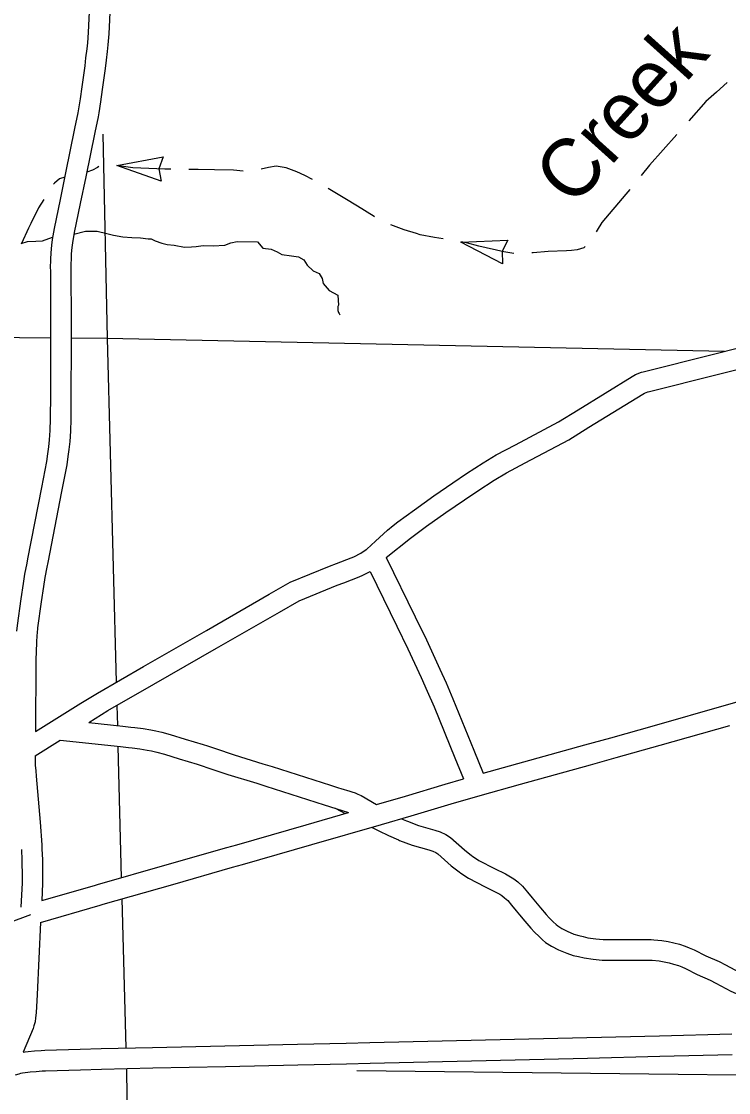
# Model space of a CAD drawing. Extents: x 1373094 to 1376427, y 1168361 to 1170494.
# Drawn here: x 1373845.2 to 1373931.1, y 1170254.2 to 1170384.4 of the extents above; entities that cross this region are included whole.
import ezdxf

# ---------------------------------------------------------------- set-up
doc = ezdxf.new("R2010")
doc.units = 0
doc.layers.add('R_Axis', color=7, linetype='Continuous')

msp = doc.modelspace()

# ---------------------------------------------------------------- linework, layer by layer
at = {"layer": 'R_Axis'}
for p, q in [((1373856.79, 1170366.88), (1373862.41, 1170367.94)), ((1373862.41, 1170367.94), (1373861.9, 1170366.49)), ((1373862.19, 1170364.98), (1373856.79, 1170366.88)), ((1373861.9, 1170366.49), (1373862.19, 1170364.98)), ((1373898.6, 1170357.56), (1373904.31, 1170357.82)), ((1373903.67, 1170354.93), (1373898.6, 1170357.56)), ((1373904.31, 1170357.82), (1373903.61, 1170356.46)), ((1373903.61, 1170356.46), (1373903.67, 1170354.93))]:
    msp.add_line(p, q, dxfattribs=at)
for points in [[(1373853.51, 1170388.63), (1373853.47, 1170386.42), (1373853.32, 1170383.04), (1373853.23, 1170381.78), (1373853.14, 1170381.05), (1373853.01, 1170379.98)], [(1373856.01, 1170388.58), (1373855.97, 1170386.34), (1373855.81, 1170382.9), (1373855.72, 1170381.54), (1373855.62, 1170380.75), (1373855.49, 1170379.68)], [(1373853.01, 1170379.98), (1373852.89, 1170378.98), (1373852.55, 1170376.46), (1373852.35, 1170374.97), (1373852.16, 1170373.75), (1373852.06, 1170373.29), (1373851.67, 1170371.39)], [(1373855.49, 1170379.68), (1373855.37, 1170378.66), (1373855.02, 1170376.12), (1373854.82, 1170374.62), (1373854.62, 1170373.3), (1373854.51, 1170372.78), (1373854.12, 1170370.88)], [(1373930.96, 1170376.96), (1373929.67, 1170375.81), (1373928.38, 1170374.64), (1373926.3, 1170372.31)], [(1373851.67, 1170371.39), (1373850.57, 1170365.99), (1373849.91, 1170362.77)], [(1373854.12, 1170370.88), (1373853.02, 1170365.49), (1373852.36, 1170362.26)], [(1373855.08, 1170370.69), (1373855.61, 1170345.9), (1373856.72, 1170304.09)], [(1373924.84, 1170370.66), (1373921.5, 1170366.92), (1373920.5, 1170365.68)], [(1373854.62, 1170366.77), (1373854.45, 1170366.63), (1373853.85, 1170366.31), (1373853.14, 1170366.08)], [(1373863.36, 1170366.43), (1373862.63, 1170366.45), (1373858.75, 1170366.58), (1373857.61, 1170366.78), (1373856.79, 1170366.88)], [(1373872.16, 1170366.21), (1373870.99, 1170366.3), (1373868.66, 1170366.37), (1373866.66, 1170366.41), (1373865.56, 1170366.41)], [(1373880.57, 1170365.17), (1373879.64, 1170365.65), (1373878.68, 1170366.11), (1373877.37, 1170366.6), (1373876.14, 1170366.81), (1373875.24, 1170366.64), (1373874.33, 1170366.44)], [(1373850.46, 1170365.45), (1373849.83, 1170365.27), (1373849.22, 1170364.75), (1373849.1, 1170364.6)], [(1373888.12, 1170360.66), (1373888.07, 1170360.69), (1373886.03, 1170361.94), (1373884.52, 1170362.87), (1373882.49, 1170364.1)], [(1373919.12, 1170363.97), (1373918.66, 1170363.41), (1373915.73, 1170359.96), (1373915.15, 1170359.01), (1373915.02, 1170358.82)], [(1373847.91, 1170362.75), (1373847.3, 1170361.73), (1373846.35, 1170359.85)], [(1373849.91, 1170362.77), (1373849.18, 1170359.22), (1373848.94, 1170357.89), (1373848.84, 1170357.19), (1373848.77, 1170356.29), (1373848.73, 1170355.51), (1373848.72, 1170355.08), (1373848.71, 1170354.79), (1373848.72, 1170353.81)], [(1373852.36, 1170362.26), (1373851.63, 1170358.75), (1373851.41, 1170357.5), (1373851.33, 1170356.91), (1373851.26, 1170356.13), (1373851.23, 1170355.43), (1373851.22, 1170355), (1373851.21, 1170354.75), (1373851.22, 1170353.83)], [(1373846.35, 1170359.85), (1373846.06, 1170359.27), (1373845.21, 1170357.41)], [(1373893.2, 1170358.6), (1373891.7, 1170359.05), (1373890.08, 1170359.67)], [(1373845.19, 1170357.41), (1373845.96, 1170357.65), (1373846.96, 1170357.7), (1373847.75, 1170357.73), (1373848.99, 1170358.19)], [(1373851.59, 1170358.55), (1373852.99, 1170358.89), (1373854.4, 1170358.91), (1373855.57, 1170358.63), (1373856.39, 1170358.41), (1373857.53, 1170358.2), (1373858.63, 1170358.13), (1373859.66, 1170358.1), (1373860.61, 1170357.98), (1373860.98, 1170357.97), (1373861.47, 1170357.73), (1373862.27, 1170357.45), (1373862.91, 1170357.3), (1373863.76, 1170357.2), (1373865, 1170356.95), (1373865.86, 1170357.01), (1373866.42, 1170357.05), (1373867.29, 1170357.17), (1373868.5, 1170357.13), (1373869.93, 1170357.22), (1373870.63, 1170357.47), (1373871.42, 1170357.66), (1373873.87, 1170357.59), (1373874.55, 1170356.82), (1373875.55, 1170356.71), (1373876.27, 1170356.4), (1373876.83, 1170356.05), (1373878.02, 1170355.92), (1373878.88, 1170355.77), (1373879.51, 1170355.43), (1373879.92, 1170354.76), (1373880.67, 1170354.07), (1373881.37, 1170353.75), (1373881.74, 1170353.14), (1373881.85, 1170352.54), (1373882.61, 1170351.71), (1373883.66, 1170351.14), (1373883.75, 1170349.93), (1373883.64, 1170349.74), (1373883.65, 1170349.27), (1373883.75, 1170349.04), (1373883.81, 1170348.89), (1373883.89, 1170348.74)], [(1373896.44, 1170357.98), (1373895.39, 1170358.14), (1373893.64, 1170358.47), (1373893.2, 1170358.6)], [(1373905.05, 1170356.18), (1373903.83, 1170356.41), (1373900.79, 1170357.08), (1373899.27, 1170357.47), (1373898.61, 1170357.6)], [(1373913.72, 1170357.06), (1373913.54, 1170356.89), (1373912.73, 1170356.63), (1373912.05, 1170356.54), (1373911.42, 1170356.51), (1373909.21, 1170356.42), (1373907.4, 1170356.28), (1373907.24, 1170356.26)], [(1373848.72, 1170353.81), (1373848.75, 1170348.15), (1373848.74, 1170345.02)], [(1373851.22, 1170353.83), (1373851.25, 1170348.16), (1373851.24, 1170345.01)], [(1373929.29, 1170343.97), (1373935.37, 1170345.49), (1373937.78, 1170346.17)], [(1373841.16, 1170346.01), (1373848.74, 1170345.95)], [(1373848.74, 1170345.02), (1373848.72, 1170338.94), (1373848.69, 1170336.23)], [(1373851.24, 1170345.01), (1373851.22, 1170338.92), (1373851.19, 1170336.21)], [(1373851.24, 1170345.93), (1373855.61, 1170345.9), (1373930.65, 1170344.31)], [(1373920.76, 1170341.83), (1373929.29, 1170343.97)], [(1373929.9, 1170341.54), (1373936.02, 1170343.08), (1373938.45, 1170343.76)], [(1373912.85, 1170337.19), (1373919.43, 1170341.26), (1373919.82, 1170341.49), (1373920.56, 1170341.78), (1373920.76, 1170341.83)], [(1373921.36, 1170339.4), (1373929.9, 1170341.54)], [(1373914.16, 1170335.07), (1373920.72, 1170339.11), (1373920.92, 1170339.23), (1373921.33, 1170339.4), (1373921.36, 1170339.4)], [(1373905.24, 1170332.95), (1373910.46, 1170335.72), (1373912.85, 1170337.19)], [(1373848.69, 1170336.23), (1373848.69, 1170336.1), (1373848.65, 1170334.7), (1373848.58, 1170333.55), (1373848.5, 1170332.68), (1373848.39, 1170331.86), (1373848.24, 1170330.93), (1373847.63, 1170327.74)], [(1373851.19, 1170336.21), (1373851.19, 1170336.05), (1373851.15, 1170334.59), (1373851.08, 1170333.36), (1373850.98, 1170332.39), (1373850.86, 1170331.51), (1373850.71, 1170330.5), (1373850.08, 1170327.27)], [(1373906.41, 1170330.74), (1373911.71, 1170333.55), (1373914.16, 1170335.07)], [(1373897.61, 1170328.31), (1373899.29, 1170329.46), (1373901.32, 1170330.76), (1373902.9, 1170331.71), (1373905.24, 1170332.95)], [(1373899.02, 1170326.24), (1373900.67, 1170327.37), (1373902.64, 1170328.63), (1373904.13, 1170329.53), (1373906.41, 1170330.74)], [(1373890.38, 1170323.14), (1373890.95, 1170323.6), (1373892.95, 1170325.06), (1373895.33, 1170326.76), (1373897.61, 1170328.31)], [(1373847.63, 1170327.74), (1373845.95, 1170319.1)], [(1373850.08, 1170327.27), (1373848.41, 1170318.63)], [(1373889.51, 1170319.25), (1373892.47, 1170321.61), (1373894.41, 1170323.04), (1373896.76, 1170324.71), (1373899.02, 1170326.24)], [(1373883.47, 1170318.51), (1373885.28, 1170319.21), (1373885.61, 1170319.35), (1373886.43, 1170319.79), (1373887.1, 1170320.21), (1373887.19, 1170320.28), (1373888.24, 1170321.23), (1373889.69, 1170322.59), (1373890.38, 1170323.14)], [(1373845.95, 1170319.1), (1373845.85, 1170318.56), (1373845.59, 1170317.21), (1373845.42, 1170316.08), (1373845.15, 1170314.24), (1373844.68, 1170311), (1373844.61, 1170310.29)], [(1373889.51, 1170319.25), (1373893.06, 1170312.03)], [(1373848.41, 1170318.63), (1373848.3, 1170318.08), (1373848.05, 1170316.8), (1373847.9, 1170315.72), (1373847.62, 1170313.88), (1373847.17, 1170310.7), (1373847.1, 1170310.05)], [(1373875.31, 1170314.78), (1373877.86, 1170316.25), (1373882.64, 1170318.19), (1373883.47, 1170318.51)], [(1373884.37, 1170316.18), (1373886.24, 1170316.9), (1373886.7, 1170317.1), (1373887.56, 1170317.55)], [(1373887.56, 1170317.55), (1373890.81, 1170310.92)], [(1373876.55, 1170312.61), (1373878.96, 1170314), (1373883.56, 1170315.87), (1373884.37, 1170316.18)], [(1373867.68, 1170310.39), (1373875.31, 1170314.78)], [(1373868.92, 1170308.23), (1373876.55, 1170312.61)], [(1373893.06, 1170312.03), (1373894.42, 1170309.24), (1373896.06, 1170305.69), (1373896.8, 1170304)], [(1373847.1, 1170310.05), (1373847.08, 1170309.8), (1373847.02, 1170308.93), (1373846.95, 1170306.76), (1373846.94, 1170303.35), (1373846.93, 1170301.37)], [(1373860.05, 1170306.01), (1373867.68, 1170310.39)], [(1373890.81, 1170310.92), (1373892.17, 1170308.17), (1373893.78, 1170304.66), (1373894.51, 1170303)], [(1373861.29, 1170303.84), (1373868.92, 1170308.23)], [(1373852.42, 1170301.53), (1373854.44, 1170302.78), (1373860.05, 1170306.01)], [(1373853.39, 1170299.19), (1373855.72, 1170300.64), (1373861.29, 1170303.84)], [(1373896.8, 1170304), (1373897.64, 1170302.07), (1373900.18, 1170295.84)], [(1373930.6, 1170301.25), (1373939.07, 1170303.66)], [(1373894.51, 1170303), (1373895.34, 1170301.1), (1373897.87, 1170294.9)], [(1373846.92, 1170298.12), (1373852.42, 1170301.53)], [(1373846.93, 1170301.37), (1373846.92, 1170298.12)], [(1373856.79, 1170301.25), (1373856.86, 1170298.83)], [(1373922.14, 1170298.85), (1373930.6, 1170301.25)], [(1373853.39, 1170299.19), (1373857.53, 1170298.76), (1373858.51, 1170298.64)], [(1373858.51, 1170298.64), (1373858.98, 1170298.59), (1373859.98, 1170298.45), (1373860.91, 1170298.3), (1373861.54, 1170298.18), (1373862.26, 1170298.01), (1373863.27, 1170297.74), (1373865.09, 1170297.19), (1373867.27, 1170296.52)], [(1373913.68, 1170296.47), (1373916.81, 1170297.33), (1373922.14, 1170298.85)], [(1373922.82, 1170296.44), (1373931.29, 1170298.85)], [(1373846.86, 1170295.14), (1373849.92, 1170297.04)], [(1373849.92, 1170297.04), (1373857.25, 1170296.27), (1373858.23, 1170296.16)], [(1373856.92, 1170296.3), (1373857.34, 1170280.34)], [(1373858.23, 1170296.16), (1373858.67, 1170296.11), (1373859.6, 1170295.98), (1373860.48, 1170295.83), (1373861.02, 1170295.74), (1373861.65, 1170295.59), (1373862.59, 1170295.34), (1373864.36, 1170294.8), (1373866.54, 1170294.13)], [(1373867.27, 1170296.52), (1373867.81, 1170296.36), (1373868.79, 1170296.02), (1373871.05, 1170295.27), (1373874.55, 1170294.19), (1373875.67, 1170293.84)], [(1373900.18, 1170295.84), (1373901.32, 1170293.04)], [(1373901.32, 1170293.04), (1373913.68, 1170296.47)], [(1373914.34, 1170294.06), (1373917.48, 1170294.93), (1373922.82, 1170296.44)], [(1373846.86, 1170295.14), (1373846.86, 1170294.74), (1373846.89, 1170294.02), (1373846.94, 1170293.33), (1373846.99, 1170292.68)], [(1373866.54, 1170294.13), (1373867.04, 1170293.98), (1373867.99, 1170293.65), (1373870.29, 1170292.89), (1373873.8, 1170291.81), (1373874.91, 1170291.45)], [(1373897.87, 1170294.9), (1373898.91, 1170292.35)], [(1373875.67, 1170293.84), (1373882.76, 1170291.57), (1373883.74, 1170291.26), (1373884.02, 1170291.18)], [(1373905.86, 1170291.71), (1373914.34, 1170294.06)], [(1373846.99, 1170292.68), (1373847.47, 1170287.07), (1373847.68, 1170284.34), (1373847.7, 1170283.86)], [(1373888.36, 1170289.24), (1373891.86, 1170290.25), (1373896.71, 1170291.69)], [(1373896.71, 1170291.69), (1373898.91, 1170292.35)], [(1373897.43, 1170289.3), (1373900.93, 1170290.34), (1373905.86, 1170291.71)], [(1373874.91, 1170291.45), (1373882, 1170289.19), (1373884.94, 1170288.26)], [(1373884.02, 1170291.18), (1373885.09, 1170290.87), (1373885.37, 1170290.78), (1373885.74, 1170290.65), (1373886.09, 1170290.51), (1373886.47, 1170290.32), (1373888.36, 1170289.24)], [(1373888.97, 1170286.81), (1373892.57, 1170287.85), (1373897.43, 1170289.3)], [(1373879.82, 1170286.78), (1373884.94, 1170288.26)], [(1373883.32, 1170288.78), (1373884.54, 1170288.14)], [(1373871.37, 1170284.35), (1373879.82, 1170286.78)], [(1373880.51, 1170284.38), (1373888.97, 1170286.81)], [(1373887.75, 1170286.46), (1373888.63, 1170286.03), (1373889.8, 1170285.46), (1373891.01, 1170284.94)], [(1373891.38, 1170287.5), (1373891.99, 1170287.24)], [(1373891.99, 1170287.24), (1373892.1, 1170287.2), (1373893.46, 1170286.67), (1373895.43, 1170286.11), (1373896.09, 1170285.9), (1373896.76, 1170285.6), (1373897.33, 1170285.22), (1373899.02, 1170283.72), (1373899.91, 1170283.04)], [(1373845.2, 1170283.76), (1373845.25, 1170282.45), (1373845.28, 1170280.41), (1373845.28, 1170279.71), (1373845.13, 1170276.74)], [(1373847.7, 1170283.86), (1373847.75, 1170282.52), (1373847.78, 1170280.42), (1373847.78, 1170279.65), (1373847.67, 1170277.55)], [(1373862.91, 1170281.93), (1373870.15, 1170284), (1373871.37, 1170284.35)], [(1373872.06, 1170281.95), (1373880.51, 1170284.38)], [(1373891.01, 1170284.94), (1373891.16, 1170284.88), (1373892.67, 1170284.3), (1373894.72, 1170283.72), (1373895.2, 1170283.56), (1373895.54, 1170283.41), (1373895.79, 1170283.24), (1373897.43, 1170281.79), (1373898.39, 1170281.06)], [(1373899.91, 1170283.04), (1373900.03, 1170282.94), (1373900.8, 1170282.44), (1373902.7, 1170281.46), (1373904.01, 1170280.8), (1373904.64, 1170280.46), (1373905.03, 1170280.19), (1373905.51, 1170279.83), (1373906.08, 1170279.32), (1373906.7, 1170278.59), (1373907.27, 1170277.88)], [(1373854.45, 1170279.51), (1373862.91, 1170281.93)], [(1373863.59, 1170279.53), (1373870.84, 1170281.6), (1373872.06, 1170281.95)], [(1373898.39, 1170281.06), (1373898.58, 1170280.91), (1373899.54, 1170280.28), (1373901.57, 1170279.23), (1373902.86, 1170278.58), (1373903.34, 1170278.32), (1373903.57, 1170278.17), (1373903.91, 1170277.91), (1373904.29, 1170277.57), (1373904.77, 1170277), (1373905.31, 1170276.32)], [(1373847.67, 1170277.55), (1373854.07, 1170279.41), (1373854.45, 1170279.51)], [(1373855.13, 1170277.11), (1373863.59, 1170279.53)], [(1373857.41, 1170277.76), (1373857.89, 1170259.65)], [(1373907.27, 1170277.88), (1373907.65, 1170277.39), (1373908.26, 1170276.68), (1373908.95, 1170275.87), (1373909.34, 1170275.47), (1373909.82, 1170274.99), (1373910.18, 1170274.67), (1373910.38, 1170274.49), (1373910.88, 1170274.17), (1373911.53, 1170273.83), (1373912.33, 1170273.49), (1373912.93, 1170273.3), (1373913.44, 1170273.18)], [(1373811.61, 1170265.69), (1373815.9, 1170266.81), (1373819.7, 1170267.91), (1373824.44, 1170269.4), (1373841.28, 1170274.05), (1373843.63, 1170274.85), (1373846.34, 1170275.86)], [(1373847.54, 1170274.91), (1373854.76, 1170277), (1373855.13, 1170277.11)], [(1373905.31, 1170276.32), (1373905.72, 1170275.81), (1373906.36, 1170275.05), (1373907.1, 1170274.19), (1373907.56, 1170273.71), (1373908.1, 1170273.18), (1373908.52, 1170272.79), (1373908.89, 1170272.48), (1373909.61, 1170272.01), (1373910.47, 1170271.56), (1373911.46, 1170271.15), (1373912.26, 1170270.89), (1373912.89, 1170270.75)], [(1373847.54, 1170274.91), (1373847.1, 1170266.16)], [(1373913.44, 1170273.18), (1373914.04, 1170273.05), (1373914.99, 1170272.91), (1373915.89, 1170272.82), (1373921.73, 1170272.82), (1373922.03, 1170272.8)], [(1373922.03, 1170272.8), (1373923.03, 1170272.71), (1373923.79, 1170272.58), (1373924.49, 1170272.43), (1373925.15, 1170272.25), (1373925.87, 1170272.01), (1373926.35, 1170271.82), (1373926.96, 1170271.58), (1373928.38, 1170270.83), (1373929.98, 1170270.14), (1373930.74, 1170269.74)], [(1373912.89, 1170270.75), (1373913.59, 1170270.59), (1373914.68, 1170270.43), (1373915.77, 1170270.32), (1373921.63, 1170270.32), (1373921.83, 1170270.3)], [(1373921.83, 1170270.3), (1373922.71, 1170270.23), (1373923.3, 1170270.12), (1373923.9, 1170270), (1373924.44, 1170269.85), (1373925.03, 1170269.66), (1373925.43, 1170269.5), (1373925.9, 1170269.31), (1373927.3, 1170268.57), (1373928.9, 1170267.89), (1373929.56, 1170267.53)], [(1373930.74, 1170269.74), (1373932.49, 1170268.81), (1373935.02, 1170267.7), (1373935.66, 1170267.34), (1373936.1, 1170267.04), (1373936.84, 1170266.4), (1373937.73, 1170265.55), (1373937.85, 1170265.47), (1373938.14, 1170265.34), (1373938.13, 1170265.34)], [(1373929.56, 1170267.53), (1373931.4, 1170266.56), (1373933.91, 1170265.45), (1373934.35, 1170265.21), (1373934.57, 1170265.06), (1373935.16, 1170264.55), (1373936.17, 1170263.58), (1373936.66, 1170263.27), (1373937.16, 1170263.04), (1373937.18, 1170263.03)], [(1373847.1, 1170266.16), (1373846.99, 1170263.93), (1373846.93, 1170263.32), (1373846.86, 1170262.83), (1373846.73, 1170262.34), (1373846.62, 1170262.02), (1373845.4, 1170259.15)], [(1373878.73, 1170260.1), (1373884.65, 1170260.23), (1373887.53, 1170260.3)], [(1373887.53, 1170260.3), (1373896.32, 1170260.51)], [(1373896.32, 1170260.51), (1373905.12, 1170260.72)], [(1373905.12, 1170260.72), (1373913.92, 1170260.93)], [(1373913.92, 1170260.93), (1373922.72, 1170261.14)], [(1373922.72, 1170261.14), (1373931.51, 1170261.35)], [(1373845.4, 1170259.15), (1373845.67, 1170259.18), (1373846.01, 1170259.22), (1373846.79, 1170259.3), (1373847.6, 1170259.35), (1373848.04, 1170259.37), (1373852.33, 1170259.5)], [(1373852.33, 1170259.5), (1373854.89, 1170259.58), (1373861.14, 1170259.72)], [(1373861.14, 1170259.72), (1373869.93, 1170259.91)], [(1373869.93, 1170259.91), (1373878.73, 1170260.1)], [(1373878.79, 1170257.6), (1373884.71, 1170257.73), (1373887.59, 1170257.8)], [(1373887.59, 1170257.8), (1373896.38, 1170258.01)], [(1373896.38, 1170258.01), (1373905.18, 1170258.22)], [(1373905.18, 1170258.22), (1373913.98, 1170258.43)], [(1373913.98, 1170258.43), (1373922.78, 1170258.64)], [(1373922.78, 1170258.64), (1373931.57, 1170258.85)], [(1373844.5, 1170256.37), (1373844.95, 1170256.52), (1373845.14, 1170256.57), (1373845.35, 1170256.61), (1373845.65, 1170256.66), (1373846, 1170256.71), (1373846.27, 1170256.74), (1373846.99, 1170256.81), (1373847.73, 1170256.86), (1373848.12, 1170256.87), (1373852.4, 1170257)], [(1373852.4, 1170257), (1373854.95, 1170257.08), (1373861.19, 1170257.22)], [(1373857.96, 1170257.15), (1373858.98, 1170169.73)], [(1373861.19, 1170257.22), (1373869.99, 1170257.41)], [(1373869.99, 1170257.41), (1373878.79, 1170257.6)], [(1373885.97, 1170256.91), (1373942.74, 1170256.26)]]:
    msp.add_lwpolyline(points, dxfattribs=at)

# ---------------------------------------------------------------- texts
msp.add_text('Creek', height=7.04, rotation=48.0073, dxfattribs=at).set_placement((1373912.22, 1170361.66))

doc.saveas('drawing.dxf')
